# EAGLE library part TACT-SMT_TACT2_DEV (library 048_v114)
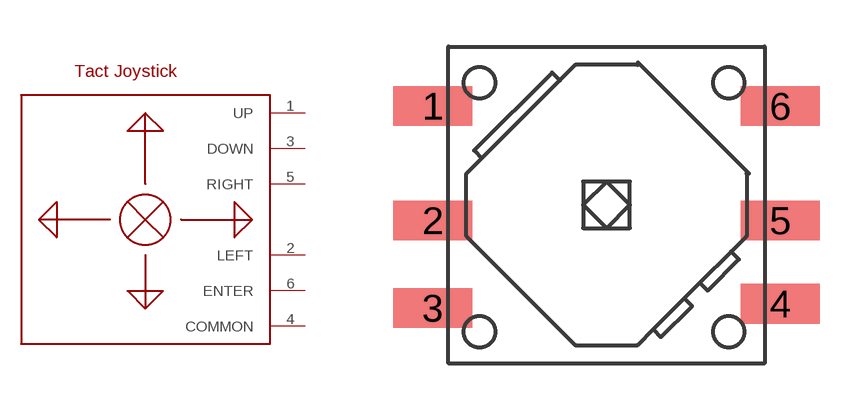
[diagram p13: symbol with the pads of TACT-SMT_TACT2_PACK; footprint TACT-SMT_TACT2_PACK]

Designator prefix -

## TACT-SMT_TACT2_DEV  [TACT-SMT_TACT2_PACK]
1  UP
2  LEFT
3  DOWN
4  COMMON
5  RIGHT
6  ENTER

## Footprint TACT-SMT_TACT2_PACK (pad centres in mm)
smd 2.54 x 1.27: 1 -5.58,3.175; 2 -5.58,-0.5; 3 -5.58,-3.31; 4 5.58,-3.175; 5 5.58,-0.5; 6 5.58,3.175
